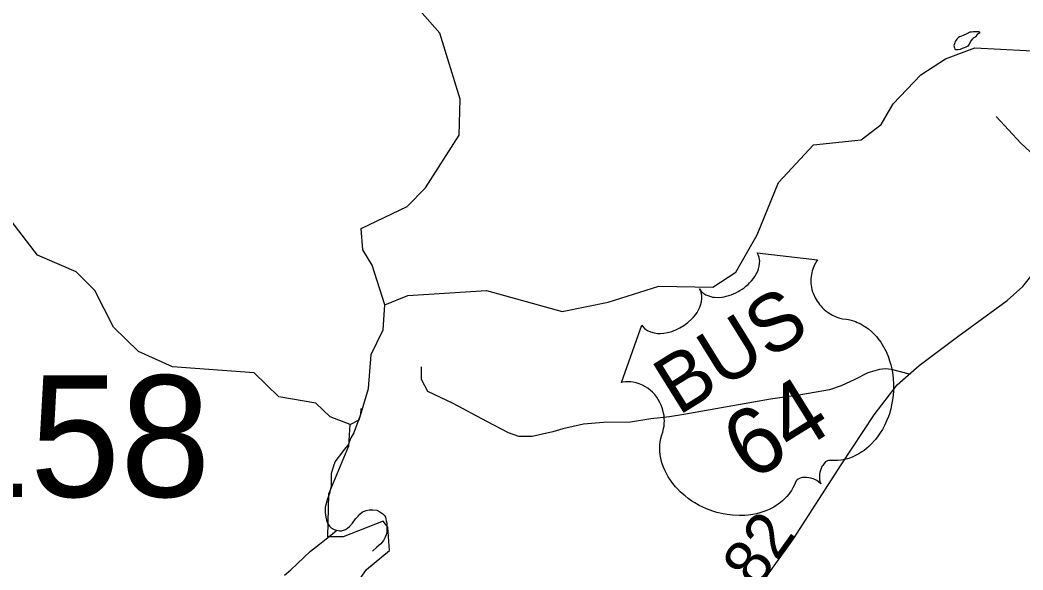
# Model space of a CAD drawing. Extents: x 2001466 to 31450019, y -30647475 to 847247.
# Drawn here: x 2191802 to 2197224, y 748208 to 751177 of the extents above; entities that cross this region are included whole.
import ezdxf

# ---------------------------------------------------------------- set-up
doc = ezdxf.new("R2010")
doc.units = 0
for name, color, linetype in [('Exist Hydrographic Creek Single Shore', 7, 'Continuous'), ('Exist Hydrographic Misc Water Feature', 7, 'Continuous'), ('Exist Road Non-System Type 51', 7, 'Continuous'), ('Exist Road Primary US Attributed', 7, 'Continuous'), ('Exist Road Primary US Mileage Hundredths English Label', 7, 'Continuous'), ('Exist Road Primary US Shield CELL', 7, 'Continuous'), ('Exist Road Primary US Shield Number Label', 7, 'Continuous'), ('Exist Road Secondary Structure Standard Bridge Number Label', 7, 'Continuous')]:
    doc.layers.add(name, color=color, linetype=linetype)

msp = doc.modelspace()

# ---------------------------------------------------------------- linework, layer by layer
at = {"layer": 'Exist Hydrographic Creek Single Shore'}
for points in [[(2193773.9, 749638.9), (2193704.8, 749853.5), (2193655, 749936.5), (2193646, 750051.6), (2193894.9, 750171.1), (2193993.9, 750270.8), (2194175, 750555.7), (2194182, 750749.1), (2194071.8, 751105.6), (2193963, 751229.2), (2193961.9, 751278.4)], [(2193585.9, 748993.3), (2193477.8, 749034.8), (2193401.9, 749108.5), (2193201.8, 749142.2), (2193067.9, 749272.8), (2192625.8, 749304.9), (2192441.9, 749387.4), (2192308, 749518.1), (2192206.9, 749716.9), (2192105.8, 749817.4), (2191896.9, 749907), (2191711.9, 750147), (2191595.8, 750198.5), (2191403.9, 750169.7), (2191221, 750101.3)], [(2193585.9, 748993.3), (2193635.9, 749018.5), (2193684.9, 749188), (2193699.9, 749371.4), (2193765.9, 749504.5), (2193773.9, 749638.9)], [(2195110.5, 747074.3), (2194953.7, 747110.9), (2194607.9, 746994.3), (2194531.8, 747110.6), (2194521.9, 747409.3), (2194462.9, 747509), (2194236.9, 747690.7), (2193943.9, 747896.8), (2193834.8, 747928.6), (2193576.9, 747927.3), (2193551.8, 747960.6), (2193559.8, 748045.7), (2193674.9, 748210.7), (2193798.9, 748313.1), (2193789.9, 748438), (2193764.9, 748471.3), (2193549, 748387.1), (2193465.9, 748385.6), (2193471.9, 748618.3), (2193578.9, 748878.6), (2193585.9, 748993.3)]]:
    msp.add_lwpolyline(points, dxfattribs=at)
at = {"layer": 'Exist Hydrographic Misc Water Feature'}
for points in [[(2193773.9, 749638.9), (2193898, 749688.9), (2194322.8, 749716.2), (2194731.9, 749602.9), (2194980.8, 749653.5), (2195255.8, 749739.7), (2195546.8, 749733.8), (2195671.9, 749816.5), (2195786.9, 750017.5), (2195901.9, 750300.5), (2196091.8, 750503.3), (2196349.8, 750530.8), (2196456.8, 750613.9), (2196522.8, 750724), (2196671.9, 750881.8), (2196804.8, 750967.6), (2196962.9, 751026.7), (2197380, 751005), (2197661.9, 751173.1), (2198110.8, 751275.4), (2198301.9, 751350.2), (2198333.2, 751374.6)], [(2196990.4, 751107.4), (2196990.6, 751111.4), (2196984.4, 751113.1), (2196976.4, 751113.1), (2196972.1, 751113.4), (2196964.5, 751113.3), (2196954.3, 751113.2), (2196946.3, 751111.2), (2196936.4, 751111.1), (2196920.6, 751102.9), (2196900.5, 751094.6), (2196890.7, 751090.8), (2196880.7, 751086.6), (2196872.9, 751080.5), (2196866.7, 751074.5), (2196862.8, 751068.6), (2196856.7, 751060.6), (2196854.8, 751054.4), (2196853, 751048.6), (2196850.7, 751040.4), (2196851.1, 751034.3), (2196851.1, 751030.2), (2196853.2, 751026.3), (2196855, 751020.3)], [(2196990.4, 751107.4), (2196976.6, 751099.3), (2196970.7, 751091.3), (2196968.6, 751087.1), (2196954.5, 751079.1), (2196952.6, 751074.9), (2196948.5, 751073.1), (2196944.4, 751067.2), (2196933.1, 751047), (2196928.6, 751040.8), (2196924.9, 751036.9), (2196915.1, 751030.7), (2196905.1, 751026.9), (2196895, 751022.8), (2196885, 751018.6), (2196871, 751016.7), (2196867.1, 751016.4), (2196861.2, 751016.5), (2196855, 751020.3)], [(2193643.7, 749078.9), (2193641.9, 749046.8), (2193632.2, 749017), (2193616.4, 748978.8), (2193606.4, 748948.6), (2193590.6, 748920.6), (2193575.4, 748882.4), (2193555.1, 748858.2), (2193533.6, 748830.3), (2193513.7, 748806.1), (2193505.9, 748793.9), (2193497.7, 748776), (2193484.2, 748725.7), (2193484.4, 748686), (2193484.8, 748662), (2193479, 748637.7), (2193474.7, 748620.1), (2193469, 748605.9), (2193463.1, 748585.7), (2193455.3, 748559.8), (2193451.4, 748545.8), (2193451.6, 748531.9), (2193451.4, 748517.8), (2193455.9, 748491.9), (2193457.9, 748475.8), (2193463.9, 748459.9), (2193474.3, 748444.1), (2193484.2, 748434.1), (2193500.2, 748426), (2193514.1, 748422.3)], [(2193514.1, 748422.3), (2193528.3, 748418.5), (2193540.2, 748418.3), (2193550.2, 748422.5), (2193561.9, 748426.4), (2193572.3, 748432.6), (2193582.2, 748442.8), (2193600, 748460.8), (2193616, 748482.8), (2193629.3, 748497), (2193639.4, 748509.2), (2193653.3, 748521.3), (2193663.4, 748525), (2193673.4, 748529.3), (2193689.4, 748531.2), (2193709.5, 748531.5), (2193731.3, 748529.8), (2193747.5, 748521.7), (2193763.7, 748509.9), (2193771.7, 748502.2), (2193777.6, 748492), (2193779.7, 748483.9), (2193782.1, 748472.2), (2193784, 748460.2), (2193785.6, 748448.2), (2193784.2, 748434.2), (2193784.2, 748413.9), (2193780.5, 748396.2), (2193776.4, 748384.3), (2193766.9, 748365.8), (2193752.4, 748348.1), (2193730.6, 748329.9), (2193706.9, 748309.6)], [(2193232.2, 748178.5), (2193265.6, 748208.7), (2193299.4, 748240.9), (2193335.3, 748274.9), (2193372.8, 748309.3), (2193420.8, 748347.5), (2193456.7, 748375.8), (2193490.3, 748402), (2193514.1, 748422.3)]]:
    msp.add_lwpolyline(points, dxfattribs=at)
at = {"layer": 'Exist Road Non-System Type 51'}
for points in [[(2197561.6, 750239.7), (2197443.5, 750330.1), (2197287.8, 750441.3), (2197211.3, 750512.9), (2197078.2, 750655.6)], [(2196609.9, 749265.4), (2196512.8, 749290.1), (2196480.4, 749294.4), (2196448.4, 749289.9), (2196384.3, 749271.5), (2196315.2, 749235.9), (2196241, 749201), (2196178.3, 749180), (2196022.7, 749152.5), (2195858, 749129.6), (2195391.1, 749047.2), (2195313.3, 749033.5), (2195212.6, 749024.3), (2195102.8, 749006), (2194956.4, 749004.4), (2194847.3, 748995.6), (2194736, 748969.4), (2194681.4, 748954.1), (2194570.1, 748927.9), (2194498.1, 748927.9), (2194442.2, 748948.7), (2194325.5, 749009.1), (2194143.5, 749106.8), (2194006.9, 749171.6), (2193972, 749235.9), (2193972, 749303.6)]]:
    msp.add_lwpolyline(points, dxfattribs=at)
at = {"layer": 'Exist Road Primary US Attributed'}
msp.add_lwpolyline([(2195110.5, 747074.3), (2195171.3, 747166.7), (2195311.9, 747385.6), (2195534.2, 747714.4), (2195766, 748071.5), (2195983.6, 748375.2), (2196240.5, 748775.2), (2196418.9, 749045.3), (2196542.9, 749206.6), (2196662.2, 749311.3), (2196871.5, 749467.3), (2197138.9, 749662.1), (2197223.6, 749737.5), (2197302.1, 749837), (2197472.1, 750089.3), (2197621.8, 750336.5)], dxfattribs=at)
at = {"layer": 'Exist Road Primary US Shield CELL'}
msp.add_lwpolyline([(2195162.7, 749530.2), (2195168.9, 749521.5), (2195177.7, 749512.2), (2195182.8, 749507.7), (2195194.5, 749500.2), (2195210.5, 749492.8), (2195229.7, 749487.8), (2195249.4, 749485.2), (2195261.7, 749485), (2195281.5, 749486.2), (2195302.9, 749489.7), (2195325.1, 749496), (2195346.7, 749504.1), (2195369.1, 749514.8), (2195390.1, 749527.4), (2195411.5, 749543), (2195433.3, 749563.2), (2195442.9, 749573.3), (2195453, 749585.7), (2195461.8, 749598), (2195470.5, 749613), (2195476.7, 749626.3), (2195481.2, 749637.3), (2195485.9, 749655.6), (2195488, 749672.8), (2195487.8, 749681.7), (2195487.3, 749690), (2195483.7, 749706), (2195481.4, 749712.6), (2195474.8, 749725.2), (2195481.8, 749715.6), (2195486.8, 749709.9), (2195492.3, 749704.7), (2195499, 749699.8), (2195509.4, 749693.4), (2195519.4, 749688.8), (2195536.3, 749683.4), (2195545.9, 749681.5), (2195554.3, 749680.5), (2195575.4, 749679.5), (2195598.2, 749681.5), (2195609.1, 749683.1), (2195619.8, 749685.5), (2195633, 749689), (2195646.1, 749693.5), (2195658.7, 749698.6), (2195671.3, 749704.1), (2195683.7, 749710.6), (2195693.6, 749716.4), (2195705.4, 749723.9), (2195715.9, 749731.4), (2195726.3, 749739.7), (2195737.4, 749749.4), (2195746, 749757.8), (2195757, 749769.5), (2195766.2, 749781.1), (2195773.8, 749792.1), (2195782.9, 749807.7), (2195789.6, 749821.3), (2195793.6, 749832.8), (2195797.7, 749847.5), (2195800.2, 749863.5), (2195800.7, 749874.5), (2195799.6, 749884.6), (2195797.9, 749895.1), (2195794.6, 749905.2), (2195790.9, 749913.4), (2195787, 749920.1), (2196113.7, 749882.1), (2196109.7, 749877), (2196101.5, 749863.8), (2196095.5, 749852.4), (2196087.1, 749832.4), (2196084.3, 749822.6), (2196081.6, 749812.5), (2196079.7, 749802.4), (2196078.3, 749793.1), (2196077.4, 749780.4), (2196077.2, 749768), (2196077.7, 749754.9), (2196078.8, 749744), (2196083.1, 749722.3), (2196086.7, 749709.2), (2196090.5, 749698.5), (2196100.1, 749677.4), (2196105.2, 749667.7), (2196110.9, 749658.5), (2196117.5, 749649.2), (2196124.2, 749640.5), (2196131.9, 749631.8), (2196138.7, 749624.3), (2196147.9, 749615.5), (2196159.4, 749605.8), (2196171.4, 749597), (2196193.2, 749584.3), (2196218.1, 749572.9), (2196234, 749567.8), (2196248.8, 749564.1), (2196269.4, 749561.2), (2196280.7, 749559.3), (2196294.3, 749556.1), (2196317.8, 749548.8), (2196328, 749544.7), (2196338.9, 749539.8), (2196349.4, 749534.4), (2196360.4, 749528.3), (2196369.5, 749522.8), (2196388.9, 749508.8), (2196405.8, 749494.1), (2196414.3, 749486.2), (2196431.7, 749467.3), (2196439.9, 749457.7), (2196454.6, 749437.9), (2196470.4, 749412.6), (2196483.4, 749387.4), (2196496.3, 749356.6), (2196503, 749337.5), (2196509.4, 749314.5), (2196514.4, 749294.1), (2196519.9, 749263), (2196522.3, 749239.4), (2196524, 749211.1), (2196524.1, 749193.5), (2196523.5, 749174.1), (2196521.8, 749151.2), (2196518.8, 749126.1), (2196513.7, 749098.4), (2196508.8, 749077.2), (2196501.3, 749051.4), (2196496.3, 749036.5), (2196488.5, 749016.2), (2196476.7, 748990.3), (2196464, 748966.4), (2196452.5, 748947.3), (2196441.6, 748931.5), (2196426.8, 748912.1), (2196400.1, 748883.1), (2196389.9, 748873.4), (2196377.3, 748862.6), (2196365.1, 748853.2), (2196352.9, 748844.6), (2196335.9, 748834), (2196318.2, 748824.8), (2196300.8, 748817.1), (2196282, 748810.2), (2196261.4, 748804.6), (2196241.7, 748800.9), (2196220.8, 748798.8), (2196183.2, 748799), (2196172.8, 748798.3), (2196167.7, 748796.7), (2196157, 748790.7), (2196148.4, 748782.6), (2196140.9, 748772.3), (2196136.8, 748765.3), (2196132.1, 748755), (2196128.9, 748746.2), (2196125.9, 748734.5), (2196124.4, 748725.3), (2196123.4, 748718.2), (2196123.2, 748701.5), (2196124.1, 748694.2), (2196125.8, 748685), (2196130.1, 748672.7), (2196118.1, 748684.2), (2196108.5, 748690.7), (2196099, 748695.6), (2196089.9, 748699.4), (2196076.9, 748703.4), (2196065.9, 748705.7), (2196053.5, 748707.3), (2196041.4, 748707.1), (2196032.2, 748706.4), (2196024.2, 748704.8), (2196015.1, 748701.8), (2196008.4, 748698.3), (2196003.1, 748694.9), (2195996.9, 748688.7), (2195991.5, 748675.5), (2195986.1, 748663.2), (2195979.9, 748650.5), (2195971.8, 748636.5), (2195965.5, 748626.9), (2195957.5, 748616.2), (2195947.6, 748604.3), (2195936.4, 748592.5), (2195924.3, 748581.2), (2195913.4, 748571.7), (2195901.1, 748562.4), (2195889.6, 748554.7), (2195877.3, 748547.2), (2195865.2, 748541), (2195851.2, 748533.9), (2195833.2, 748526), (2195817.6, 748520.6), (2195800.8, 748515.5), (2195783, 748510.9), (2195763.4, 748507.1), (2195738.2, 748503.4), (2195719.9, 748501.9), (2195690.4, 748500.8), (2195653.8, 748502.6), (2195624.8, 748506.2), (2195602.8, 748510.2), (2195568.8, 748518.4), (2195548, 748524.6), (2195513.5, 748537.5), (2195490.1, 748547.8), (2195473.9, 748556), (2195449.2, 748569.9), (2195434.5, 748579.2), (2195414.2, 748593.4), (2195396.7, 748607), (2195380.8, 748620.4), (2195371.2, 748629.3), (2195355.5, 748645.5), (2195344.7, 748657.2), (2195330.9, 748673.9), (2195317.6, 748692.2), (2195306.3, 748709.7), (2195297.6, 748724.7), (2195288.6, 748742.9), (2195280.2, 748762.9), (2195273.9, 748780.7), (2195270.1, 748793.9), (2195266.2, 748810.5), (2195262.9, 748829.4), (2195261.2, 748848.3), (2195260.6, 748864.6), (2195261.2, 748882.9), (2195262.9, 748899.1), (2195266.5, 748918.2), (2195271.2, 748936.5), (2195276.4, 748951.8), (2195281.3, 748972.1), (2195283.3, 748983.6), (2195284.7, 748999), (2195285, 749012.6), (2195284.6, 749024.4), (2195283.3, 749041.3), (2195281.3, 749053.4), (2195277.2, 749071.2), (2195273.3, 749083.1), (2195267.6, 749098), (2195261.5, 749111.5), (2195252.4, 749127.5), (2195244, 749140.2), (2195232.9, 749154.2), (2195221.1, 749166.9), (2195209.8, 749177.4), (2195195.4, 749188.5), (2195183.8, 749196), (2195166.5, 749205.1), (2195149, 749212.6), (2195132.6, 749217.5), (2195116.9, 749221.1), (2195103.1, 749222.6), (2195090.4, 749223.4), (2195075.1, 749223.2), (2195061.1, 749221.8), (2195052.7, 749220.3)], close=True, dxfattribs=at)

# ---------------------------------------------------------------- texts
at = {"layer": 'Exist Road Primary US Mileage Hundredths English Label'}
msp.add_text('.82', height=250, rotation=54.3696, dxfattribs=at).set_placement((2195730.8, 748022.5))
at = {"layer": 'Exist Road Primary US Shield Number Label'}
for s, height, p in [('BUS', 310, (2195360.4, 749037.6)), ('64', 360, (2195751.2, 748680.5))]:
    msp.add_text(s, height=height, rotation=31.918, dxfattribs=at).set_placement(p)
at = {"layer": 'Exist Road Secondary Structure Standard Bridge Number Label'}
msp.add_text('158', height=656.17, dxfattribs=at).set_placement((2191367.5, 748602.2))

doc.saveas('drawing.dxf')
